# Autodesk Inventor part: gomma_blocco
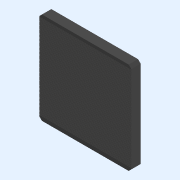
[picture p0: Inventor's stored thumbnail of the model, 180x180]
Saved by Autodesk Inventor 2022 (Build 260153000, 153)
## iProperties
Created: 2022-01
Part Number: gomma_blocco
Material: Generico
Document SubType Name: Modeling
Designer: admin
Density: 1 g/cm^3
Appearance: Gomma - Nero
Author: admin
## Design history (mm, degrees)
sketch "Schizzo1"
  geometry: L1 (23.086, 24.5)-(24.5, 23.086) reference; L2 (-23.086, 24.5)-(23.086, 24.5) reference; L3 (-24.5, 23.086)-(-23.086, 24.5) reference; L4 (-24.5, -23.086)-(-24.5, 23.086) reference; L5 (-23.086, -24.5)-(-24.5, -23.086) reference; L6 (23.086, -24.5)-(-23.086, -24.5) reference; L7 (24.5, -23.086)-(23.086, -24.5) reference; L8 (24.5, 23.086)-(24.5, -23.086) reference; C1 r 4.323 at (0, 0) reference; C2 r 3.25 at (-18, -18) reference; C3 r 3.25 at (-18, 18) reference; C4 r 3.25 at (18, -18) reference; C5 r 3.25 at (18, 18) reference; 1 further point
extrude "Estrusione1" new body sketch "Schizzo1" distance "d0" = 5; taper "d1" = 0 deg
sketch "Schizzo2"
  geometry: L1 (5, 46.172)-(5, 0) reference; L2 (0, 0)-(5, 0) reference; C1 r 0.25 at (4.75, 0.5); C2 r 0.25 at (4.75, 1); 4 further points
  constraints: 3 tangent, 2 centre point
  dimensions: "d2" = 0.5 diameter of C1; "d3" = 0.5 distance from line of L2 C1.centre
extrude "Estrusione2" cut sketch "Schizzo2" extent not by distance; stored distance "d4" = 0; taper "d5" = 0 deg
node "Solido1"
pattern_linear "Serie rettangolare1" dims "d8" = 0.5
node "Riferimento1"
